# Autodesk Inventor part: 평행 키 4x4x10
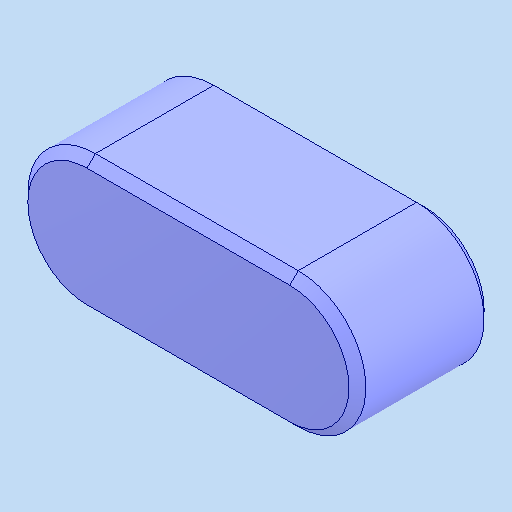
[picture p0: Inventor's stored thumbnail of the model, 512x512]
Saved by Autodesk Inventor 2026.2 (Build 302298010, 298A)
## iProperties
Created: 2026-08
Part Number: 평행 키 4x4x10
Material: 강철, 연강
Description: 키 및 해당 키홈
Document SubType Name: Modeling
Designer: PC2-02
Density: 7.85 g/cm^3
Appearance: 기본값
Author: jhkim
Sending System: Autodesk Inventor 2027
Preprocessor: ST-DEVELOPER v20.1
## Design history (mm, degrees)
feature "Solid1"
node "솔리드1"
